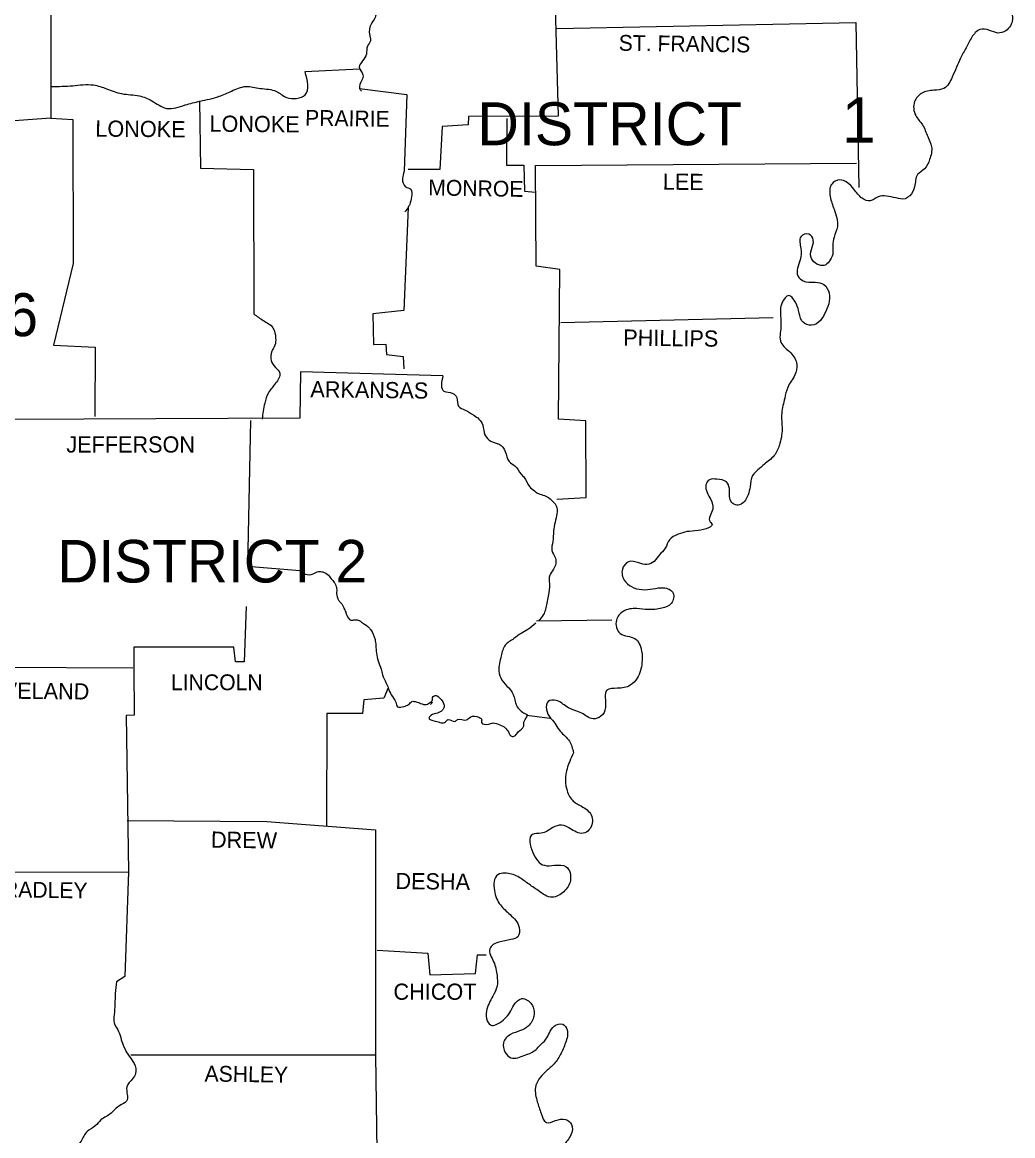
# Model space of a CAD drawing. Extents: x 166 to 3426, y 71 to 2074.
# Drawn here: x 2999.8 to 3257.2, y 1468.2 to 1757.5 of the extents above; entities that cross this region are included whole.
import ezdxf

# ---------------------------------------------------------------- set-up
doc = ezdxf.new("R2010")
doc.units = 0
for name, color, linetype in [('1', 7, 'Continuous'), ('2', 7, 'Continuous'), ('3', 7, 'Continuous')]:
    doc.layers.add(name, color=color, linetype=linetype)

msp = doc.modelspace()

# ---------------------------------------------------------------- linework, layer by layer
at = {"layer": '1'}
msp.add_line((3133.42, 1601.94), (3152.99, 1602.24), dxfattribs=at)
for points in [[(3000.75, 1956.03), (3000.95, 1932.74), (2999.28, 1932.64), (2999.58, 1908.28), (2992.73, 1907.3), (2993.32, 1900.75), (2995.66, 1897.71), (2995.47, 1889.98), (2982.16, 1889.5), (2981.67, 1877.56), (2969.54, 1877.17), (2968.95, 1862.69), (2969.64, 1861.51), (2969.93, 1838.42), (2990.87, 1837.05), (2990.58, 1785.49), (3007.21, 1785), (3007.21, 1732.56), (2994.1, 1731.58), (2993.12, 1720.04), (2971.11, 1719.94)], [(3137.53, 1786.66), (3139, 1733.05), (3115.71, 1732.95), (3115.62, 1730.8), (3108.87, 1730.41), (3108.28, 1719.25), (3100.06, 1719.25)], [(3138.71, 1755.85), (3216.39, 1757.41)], [(3216.39, 1757.41), (3217.18, 1714.56)], [(3073.25, 1744.69), (3087.44, 1745.38)], [(3087.44, 1740.29), (3099.67, 1738.72), (3098.98, 1718.76)], [(3045.86, 1737.06), (3046.05, 1719.55), (3059.85, 1719.25), (3059.95, 1681.68)], [(3007.21, 1732.56), (3012.88, 1732.17), (3012.98, 1694.79), (3007.89, 1673.56), (3018.75, 1673.07), (3018.66, 1655.07)], [(3125.69, 1732.46), (3125.6, 1720.33), (3130.1, 1720.33), (3130.29, 1713.58), (3133.13, 1713.28)], [(3138.71, 1633.54), (3146.34, 1634.03), (3146.24, 1653.9), (3139.1, 1654.38), (3139.49, 1693.23), (3133.33, 1694.11), (3133.13, 1720.23), (3216.59, 1720.82)], [(3100.06, 1709.37), (3098.89, 1682.56), (3090.86, 1681.68), (3091.06, 1673.76), (3094.29, 1673.85), (3094.39, 1671.11), (3098.79, 1670.63), (3098.89, 1667.4)], [(3139.69, 1679.43), (3194.87, 1680.8)], [(3109.06, 1665.64), (3072.08, 1666.61), (3071.88, 1654.58), (2997.03, 1654.29)], [(3059.06, 1653.99), (3058.28, 1616.13), (3071.88, 1615.05)], [(3057.99, 1605.66), (3057.4, 1591.28), (3055.15, 1591.28), (3054.76, 1595.09), (3028.73, 1595.09), (3028.73, 1589.61)], [(2993.9, 1589.91), (3028.54, 1589.71)], [(3028.73, 1589.71), (3028.83, 1577.48), (3026.78, 1577.38), (3027.36, 1536.78)], [(3094.87, 1584.53), (3093.7, 1581.88), (3088.51, 1581.4), (3088.22, 1577.87), (3078.93, 1577.87), (3078.83, 1548.62)], [(3105.83, 1580.22), (3106.13, 1580.51), (3106.42, 1580.81), (3106.42, 1580.81)], [(3027.07, 1550.09), (3063.37, 1549.79), (3091.55, 1547.64)], [(3091.55, 1547.64), (3091.55, 1489.13), (3092.33, 1432.87)], [(2983.14, 1536.68), (3027.36, 1536.78)], [(3027.36, 1536.78), (3026.39, 1509.58), (3024.23, 1508.21)], [(3092.04, 1516.43), (3105.15, 1515.65), (3105.73, 1509.97), (3117.57, 1510.36), (3118.06, 1515.16), (3120.31, 1515.16)], [(3027.95, 1489.23), (3091.55, 1489.23)]]:
    msp.add_lwpolyline(points, dxfattribs=at)
for points in [[(3099.86, 1798.01), (3099.37, 1794.79), (3097.52, 1793.91), (3095.36, 1791.75), (3094.87, 1789.8), (3093.11, 1789.01), (3091.45, 1786.96), (3090.37, 1784.12), (3090.37, 1781.19), (3091.06, 1777.86), (3093.5, 1776.98), (3094.68, 1775.02), (3094.48, 1772.97), (3096.83, 1771.6), (3097.22, 1770.42), (3096.83, 1769.15), (3095.75, 1765.53), (3095.85, 1763.09), (3095.66, 1762.01), (3093.02, 1761.32), (3091.45, 1758.68), (3090.37, 1756.82), (3089.98, 1754.38), (3090.28, 1752.62), (3089.49, 1751.25), (3089.2, 1749.19), (3088.22, 1747.43), (3087.34, 1745.77), (3088.32, 1743.81), (3088.03, 1742.44), (3087.44, 1740.29), (3087.93, 1739.6)], [(3252.89, 1794.1), (3253.28, 1791.26), (3251.62, 1788.23), (3251.03, 1785.2), (3251.32, 1782.16), (3248.19, 1780.5), (3245.45, 1778.54), (3247.02, 1776.2), (3249.95, 1774.04), (3252.89, 1772.38), (3254.75, 1770.72), (3255.24, 1766.71), (3255.72, 1764.16), (3256.7, 1760.64), (3257.09, 1758.19), (3255.33, 1755.26), (3253.28, 1754.67), (3251.13, 1755.36), (3248.58, 1755.55), (3246.53, 1753.59), (3245.06, 1750.86), (3243.59, 1748.12), (3242.52, 1745.77), (3241.44, 1743.22), (3239.29, 1740.29), (3236.65, 1739.8), (3233.51, 1739.02), (3231.66, 1736.86), (3231.95, 1733.24), (3233.71, 1730.8), (3235.08, 1727.76), (3236.06, 1725.12), (3235.57, 1721.8), (3234.2, 1719.35), (3232.44, 1717.88), (3231.66, 1714.75), (3230.38, 1712.4), (3229.21, 1711.62), (3226.86, 1711.82), (3224.32, 1712.31), (3222.16, 1712.11), (3220.11, 1711.03), (3218.06, 1711.72), (3215.9, 1714.07), (3214.14, 1715.83), (3212.19, 1716.51), (3210.13, 1715.44), (3209.74, 1712.21), (3210.72, 1708.88), (3211.6, 1704.38), (3210.72, 1701.64), (3210.42, 1697.14)], [(3007.4, 1740.78), (3012.88, 1740.97), (3018.26, 1741.17), (3021.69, 1740.19), (3025.6, 1738.92), (3030.2, 1738.33), (3033.43, 1737.06), (3037.25, 1735.1), (3042.14, 1735.98), (3045.95, 1736.96), (3050.94, 1738.23), (3054.17, 1739.6), (3057.89, 1740.78), (3061.61, 1740.29), (3065.82, 1739.51), (3068.46, 1737.94), (3073.25, 1738.63), (3073.25, 1744.69)], [(3098.98, 1718.76), (3098.59, 1716.81), (3099.37, 1714.75), (3100.74, 1714.07), (3100.94, 1712.11), (3100.45, 1710.15), (3100.06, 1709.37), (3099.18, 1708.2)], [(3210.42, 1697.14), (3208.17, 1694.3), (3204.85, 1696.06), (3204.85, 1698.41), (3205.34, 1700.86), (3204.16, 1702.42), (3202.11, 1701.74), (3202.11, 1698.71), (3201.91, 1695.77), (3201.32, 1691.56), (3202.69, 1690.29), (3205.83, 1689.9), (3208.08, 1689.31), (3209.45, 1687.06), (3209.35, 1684.32), (3208.27, 1681.68), (3206.71, 1679.53), (3204.26, 1678.75), (3202.3, 1680.02), (3201.52, 1682.56), (3200.64, 1684.81), (3198.98, 1686.48), (3197.22, 1684.62), (3196.82, 1681.19), (3196.92, 1678.26), (3196.92, 1674.25), (3199.47, 1671.6), (3201.03, 1668.57), (3200.54, 1665.83), (3198.68, 1662.6), (3197.9, 1659.77), (3197.12, 1655.95), (3197.22, 1651.74), (3196.53, 1647.63), (3195.16, 1644.89), (3192.62, 1642.64), (3190.95, 1641.18), (3189.58, 1639.71), (3188.9, 1636.77), (3188.41, 1634.72), (3186.55, 1632.27), (3185.08, 1632.08), (3183.91, 1633.05), (3183.52, 1634.72), (3183.52, 1636.38), (3182.74, 1638.04), (3180.29, 1638.73), (3178.33, 1638.63), (3177.45, 1637.26), (3178.72, 1633.45), (3179.21, 1631), (3178.53, 1627.67), (3178.92, 1627.28), (3175.4, 1625.42), (3172.56, 1625.13), (3170.21, 1624.44), (3167.96, 1622.98), (3166.88, 1620.82), (3165.32, 1619.06), (3163.95, 1617.4), (3162.09, 1616.62), (3160.04, 1617.01), (3157.3, 1617.3), (3155.73, 1615.35), (3156.22, 1612.51), (3158.08, 1610.85), (3160.82, 1610.06), (3163.66, 1610.26), (3166.4, 1610.55), (3168.94, 1609.18), (3168.45, 1606.54), (3166, 1605.27), (3162.38, 1604.88), (3159.45, 1605.17), (3155.93, 1604.39), (3154.17, 1602.14), (3155.14, 1598.71), (3158.96, 1597.34), (3160.72, 1594.11), (3160.82, 1591.08), (3159.55, 1587.07), (3157.79, 1585.21), (3154.36, 1584.43), (3151.72, 1583.94), (3151.33, 1579.44), (3150.15, 1577.19), (3148.1, 1576.5), (3145.16, 1577.97), (3143.4, 1578.66), (3141.25, 1579.63), (3138.51, 1581.3), (3136.46, 1581), (3137.04, 1576.7), (3137.24, 1576.5), (3139.59, 1573.27), (3141.94, 1570.73), (3143.01, 1567.7)], [(3059.95, 1681.68), (3062.39, 1680.02), (3064.93, 1678.06), (3065.62, 1675.42), (3065.42, 1673.56), (3064.64, 1672), (3064.45, 1669.55), (3065.62, 1667.79), (3066.7, 1666.32), (3065.62, 1663.68), (3063.76, 1661.23), (3062.78, 1658.49), (3062.1, 1654.38)], [(3109.06, 1665.64), (3109.35, 1661.62), (3111.7, 1661.04), (3112.68, 1659.96), (3113.17, 1657.71), (3114.83, 1656.73), (3117.08, 1655.36), (3118.45, 1654.38), (3119.43, 1652.82), (3120.02, 1650.27), (3121.58, 1648.61), (3123.74, 1647.83), (3125.3, 1645.97), (3126.28, 1643.33), (3127.85, 1642.15), (3129.41, 1640.1), (3130.19, 1639.22), (3131.56, 1636.87), (3132.93, 1635.7), (3133.91, 1635.01), (3135.48, 1634.52), (3137.43, 1633.25), (3138.71, 1631.29), (3138.71, 1629.83), (3138.22, 1627.58), (3137.83, 1625.23), (3137.63, 1622.59), (3137.43, 1620.24), (3138.32, 1618.28), (3137.83, 1615.35), (3136.85, 1613.78), (3136.75, 1611.63), (3136.46, 1608.4), (3136.07, 1606.54), (3135.18, 1603.51), (3133.91, 1601.94)], [(3071.88, 1615.05), (3073.35, 1614.07), (3075.4, 1614.17), (3076.77, 1614.76), (3077.85, 1614.66), (3079.32, 1613.78), (3080.3, 1612.61), (3080.98, 1611.73), (3081.47, 1610.36), (3081.47, 1609.08), (3081.96, 1607.32), (3082.55, 1606.64), (3083.33, 1605.37), (3083.82, 1604.19), (3084.11, 1603.41), (3085.19, 1602.14), (3086.17, 1602.24), (3087.05, 1602.14), (3088.22, 1601.45), (3089.98, 1600.08), (3090.28, 1599.69), (3091.45, 1597.15), (3091.65, 1595.58), (3091.84, 1593.53), (3092.23, 1591.57), (3093.02, 1589.42), (3093.41, 1587.95), (3094.29, 1585.9), (3094.87, 1584.53), (3095.66, 1582.76), (3096.83, 1580.81), (3097.32, 1579.63), (3098.98, 1579.73), (3100.16, 1580.22), (3101.04, 1581), (3102.11, 1580.91), (3103.29, 1580.51), (3104.85, 1580.22), (3105.83, 1580.81), (3106.32, 1581.2), (3106.42, 1582.08), (3107.3, 1582.57), (3108.28, 1581.88), (3109.35, 1580.32), (3109.35, 1579.34), (3108.96, 1578.75), (3107.69, 1577.97), (3105.93, 1577.38), (3105.44, 1576.7), (3107.1, 1575.92), (3109.75, 1575.72), (3110.43, 1576.31), (3112.19, 1575.82), (3112.88, 1576.31), (3115.23, 1576.21), (3116.3, 1576.99), (3118.45, 1576.89), (3119.14, 1576.41), (3119.14, 1575.52), (3120.9, 1575.13), (3122.17, 1575.43), (3123.84, 1574.94), (3125.3, 1574.15), (3126.09, 1573.08), (3127.06, 1571.9), (3127.94, 1572.2), (3128.63, 1573.08), (3130.1, 1574.64), (3130.1, 1575.62), (3130.49, 1576.31), (3130.98, 1577.29)], [(3133.23, 1601.35), (3131.17, 1599.69), (3129.41, 1598.71), (3127.55, 1597.34), (3125.3, 1595.68), (3124.23, 1592.84), (3123.64, 1588.93), (3124.42, 1586.58), (3126.18, 1584.53), (3127.36, 1582.86), (3128.24, 1579.93), (3130.39, 1577.87), (3131.08, 1577.58)], [(3143.01, 1567.7), (3142.03, 1565.45), (3140.96, 1561.53), (3141.25, 1558.21), (3142.72, 1555.37), (3145.07, 1553.8), (3147.61, 1551.55), (3147.41, 1548.13), (3145.95, 1546.86), (3142.52, 1547.74), (3139.88, 1548.91), (3137.63, 1548.23), (3134.6, 1546.76), (3132.35, 1546.47), (3132.45, 1541.77), (3135.48, 1538.44), (3138.12, 1538.44), (3141.15, 1538.05), (3142.23, 1534.53), (3140.47, 1531.59), (3137.53, 1530.13), (3133.81, 1531.89), (3131.17, 1533.75), (3128.53, 1535.51), (3125.2, 1536.39), (3123.35, 1536), (3122.47, 1531.89), (3124.03, 1528.17), (3126.57, 1525.63), (3128.92, 1522.3), (3128.53, 1519.85), (3126.77, 1519.17), (3123.64, 1518.48), (3121.78, 1517.51), (3121.29, 1516.72), (3122.27, 1513.4), (3123.15, 1509.78), (3123.15, 1507.04), (3122.07, 1504.49), (3120.41, 1500.58), (3120.61, 1498.03), (3121.78, 1496.86), (3123.25, 1497.25), (3125.2, 1498.62), (3126.48, 1500.19), (3127.55, 1502.14), (3129.61, 1503.81), (3132.15, 1502.34), (3132.74, 1499.31), (3131.27, 1496.67), (3129.22, 1495.49), (3126.67, 1494.51), (3124.81, 1492.36), (3125.3, 1489.82), (3126.77, 1488.45), (3130.39, 1489.13), (3132.84, 1490.21), (3134.21, 1491.58), (3135.87, 1493.24), (3136.75, 1494.9), (3138.02, 1496.67), (3140.27, 1497.15), (3141.35, 1495.69), (3140.96, 1492.36), (3139.59, 1489.23), (3137.73, 1486.59), (3135.67, 1484.73), (3133.13, 1480.72), (3133.62, 1477), (3134.6, 1473.97), (3135.97, 1471.62), (3138.32, 1472.11), (3140.96, 1472.4), (3142.52, 1471.13), (3142.33, 1468.39), (3140.37, 1465.75), (3138.51, 1463.2), (3137.53, 1459.68), (3137.92, 1457.24), (3137.92, 1454.98), (3137.14, 1452.54), (3135.77, 1451.17), (3132.15, 1451.27), (3128.34, 1451.66), (3126.28, 1450.48), (3126.67, 1447.16), (3128.92, 1444.71), (3130.49, 1443.44), (3132.74, 1440.7), (3133.72, 1438.45), (3133.42, 1436.49), (3132.05, 1434.83), (3128.04, 1432.87)], [(3024.23, 1508.21), (3023.94, 1505.18), (3023.84, 1502.34), (3023.65, 1499.6), (3023.65, 1497.55), (3024.82, 1495.3), (3025.51, 1493.14), (3026.19, 1491.28), (3027.56, 1488.84), (3028.83, 1486.98), (3029.22, 1484.34), (3028.44, 1482.97), (3026.97, 1480.91), (3026.87, 1477.19), (3025.11, 1476.02), (3022.86, 1474.06), (3021.59, 1473.18), (3020.22, 1472.3), (3018.75, 1470.74), (3016.6, 1469.27), (3015.04, 1466.82), (3013.28, 1464.96), (3011.81, 1463.99), (3009.75, 1462.71), (3008.87, 1460.76), (3008.19, 1457.14), (3008.48, 1454.5), (3008.87, 1452.15), (3008.38, 1449.21), (3008.87, 1445.98), (3009.36, 1443.44), (3010.14, 1441.19), (3011.22, 1438.65), (3012.59, 1436.3), (3015.53, 1432.68)], [(2926.69, 1485.61), (2928.25, 1486.69), (2929.72, 1487.27), (2931.19, 1486.98), (2932.75, 1486.78), (2934.12, 1486.98), (2935.88, 1486.69), (2937.35, 1485.8), (2939.01, 1485.12), (2940.68, 1485.12), (2942.14, 1485.12), (2943.42, 1484.24), (2945.77, 1484.34), (2947.72, 1485.12), (2949.68, 1485.71), (2952.32, 1486), (2954.67, 1484.34), (2956.33, 1482.97), (2957.7, 1481.4), (2958.68, 1479.64), (2959.76, 1478.66), (2961.52, 1477.98), (2962.89, 1477.68), (2964.55, 1477.19), (2965.43, 1476.8), (2966.21, 1474.94), (2967.49, 1472.4), (2969.93, 1471.52), (2972.96, 1472.69), (2975.41, 1473.38), (2977.17, 1473.97), (2978.25, 1474.36), (2979.23, 1474.46), (2978.93, 1474.65), (2980.11, 1474.94), (2981.18, 1474.16), (2981.87, 1473.09), (2983.04, 1471.52), (2984.12, 1470.15), (2985.19, 1469.66), (2986.27, 1470.25), (2987.74, 1469.76), (2989.01, 1469.27), (2990.48, 1468.88), (2991.75, 1468.78), (2993.41, 1468.39), (2994.69, 1467.7), (2995.86, 1467.02), (2997.03, 1465.75), (2998.21, 1463.79), (2998.6, 1462.23), (2999.97, 1460.66), (3001.24, 1460.66), (3003.1, 1458.12), (3003.78, 1457.14), (3005.25, 1455.38), (3006.33, 1455.38), (3008.38, 1454.98)]]:
    msp.add_spline(points, degree=3, dxfattribs=at)
at = {"layer": '3'}
msp.add_line((3130.78, 1577.48), (3136.95, 1576.7), dxfattribs=at)

# ---------------------------------------------------------------- texts
at = {"layer": '1'}
msp.add_text('1', height=11.74, dxfattribs=at).set_placement((3212.77, 1726.2))
at = {"layer": '2'}
for s, height, rotation, p in [('ST. FRANCIS', 4.1081, 359.2216, (3154.75, 1750.07)), ('LONOKE', 4.207, 359.4974, (3048.4, 1729.04)), ('PRAIRIE', 4.109, 359.2116, (3073.25, 1730.6)), ('LONOKE', 4.207, 359.4974, (3018.75, 1727.76)), ('MONROE', 4.108, 359.0331, (3105.25, 1712.5)), ('LEE', 4.207, 359.4327, (3166.2, 1713.97)), ('PHILLIPS', 4.206, 359.3179, (3155.93, 1673.46)), ('ARKANSAS', 4.206, 359.2678, (3074.62, 1660.06)), ('CLEVELAND', 4.207, 359.3377, (2983.73, 1581.88)), ('DREW', 4.206, 359.2258, (3048.79, 1543.04)), ('DESHA', 4.206, 359.3704, (3096.73, 1532.28)), ('BRADLEY', 4.108, 359.1449, (2991.07, 1530.22)), ('ASHLEY', 4.109, 359.2361, (3047.13, 1482.28))]:
    msp.add_text(s, height=height, rotation=rotation, dxfattribs=at).set_placement(p)
for s, height, p in [('JEFFERSON', 4.207, (3011.22, 1645.68)), ('LINCOLN', 4.109, (3038.42, 1583.94)), ('CHICOT', 4.207, (3096.24, 1503.51))]:
    msp.add_text(s, height=height, dxfattribs=at).set_placement(p)
at = {"layer": '3'}
for s, height, p in [('DISTRICT', 11.154, (3118.06, 1725.51)), ('DISTRICT 6', 11.154, (2922.67, 1675.91)), ('DISTRICT 2', 11.056, (3008.87, 1611.92))]:
    msp.add_text(s, height=height, dxfattribs=at).set_placement(p)

doc.saveas('drawing.dxf')
